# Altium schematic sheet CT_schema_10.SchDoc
size 389 x 278 mm
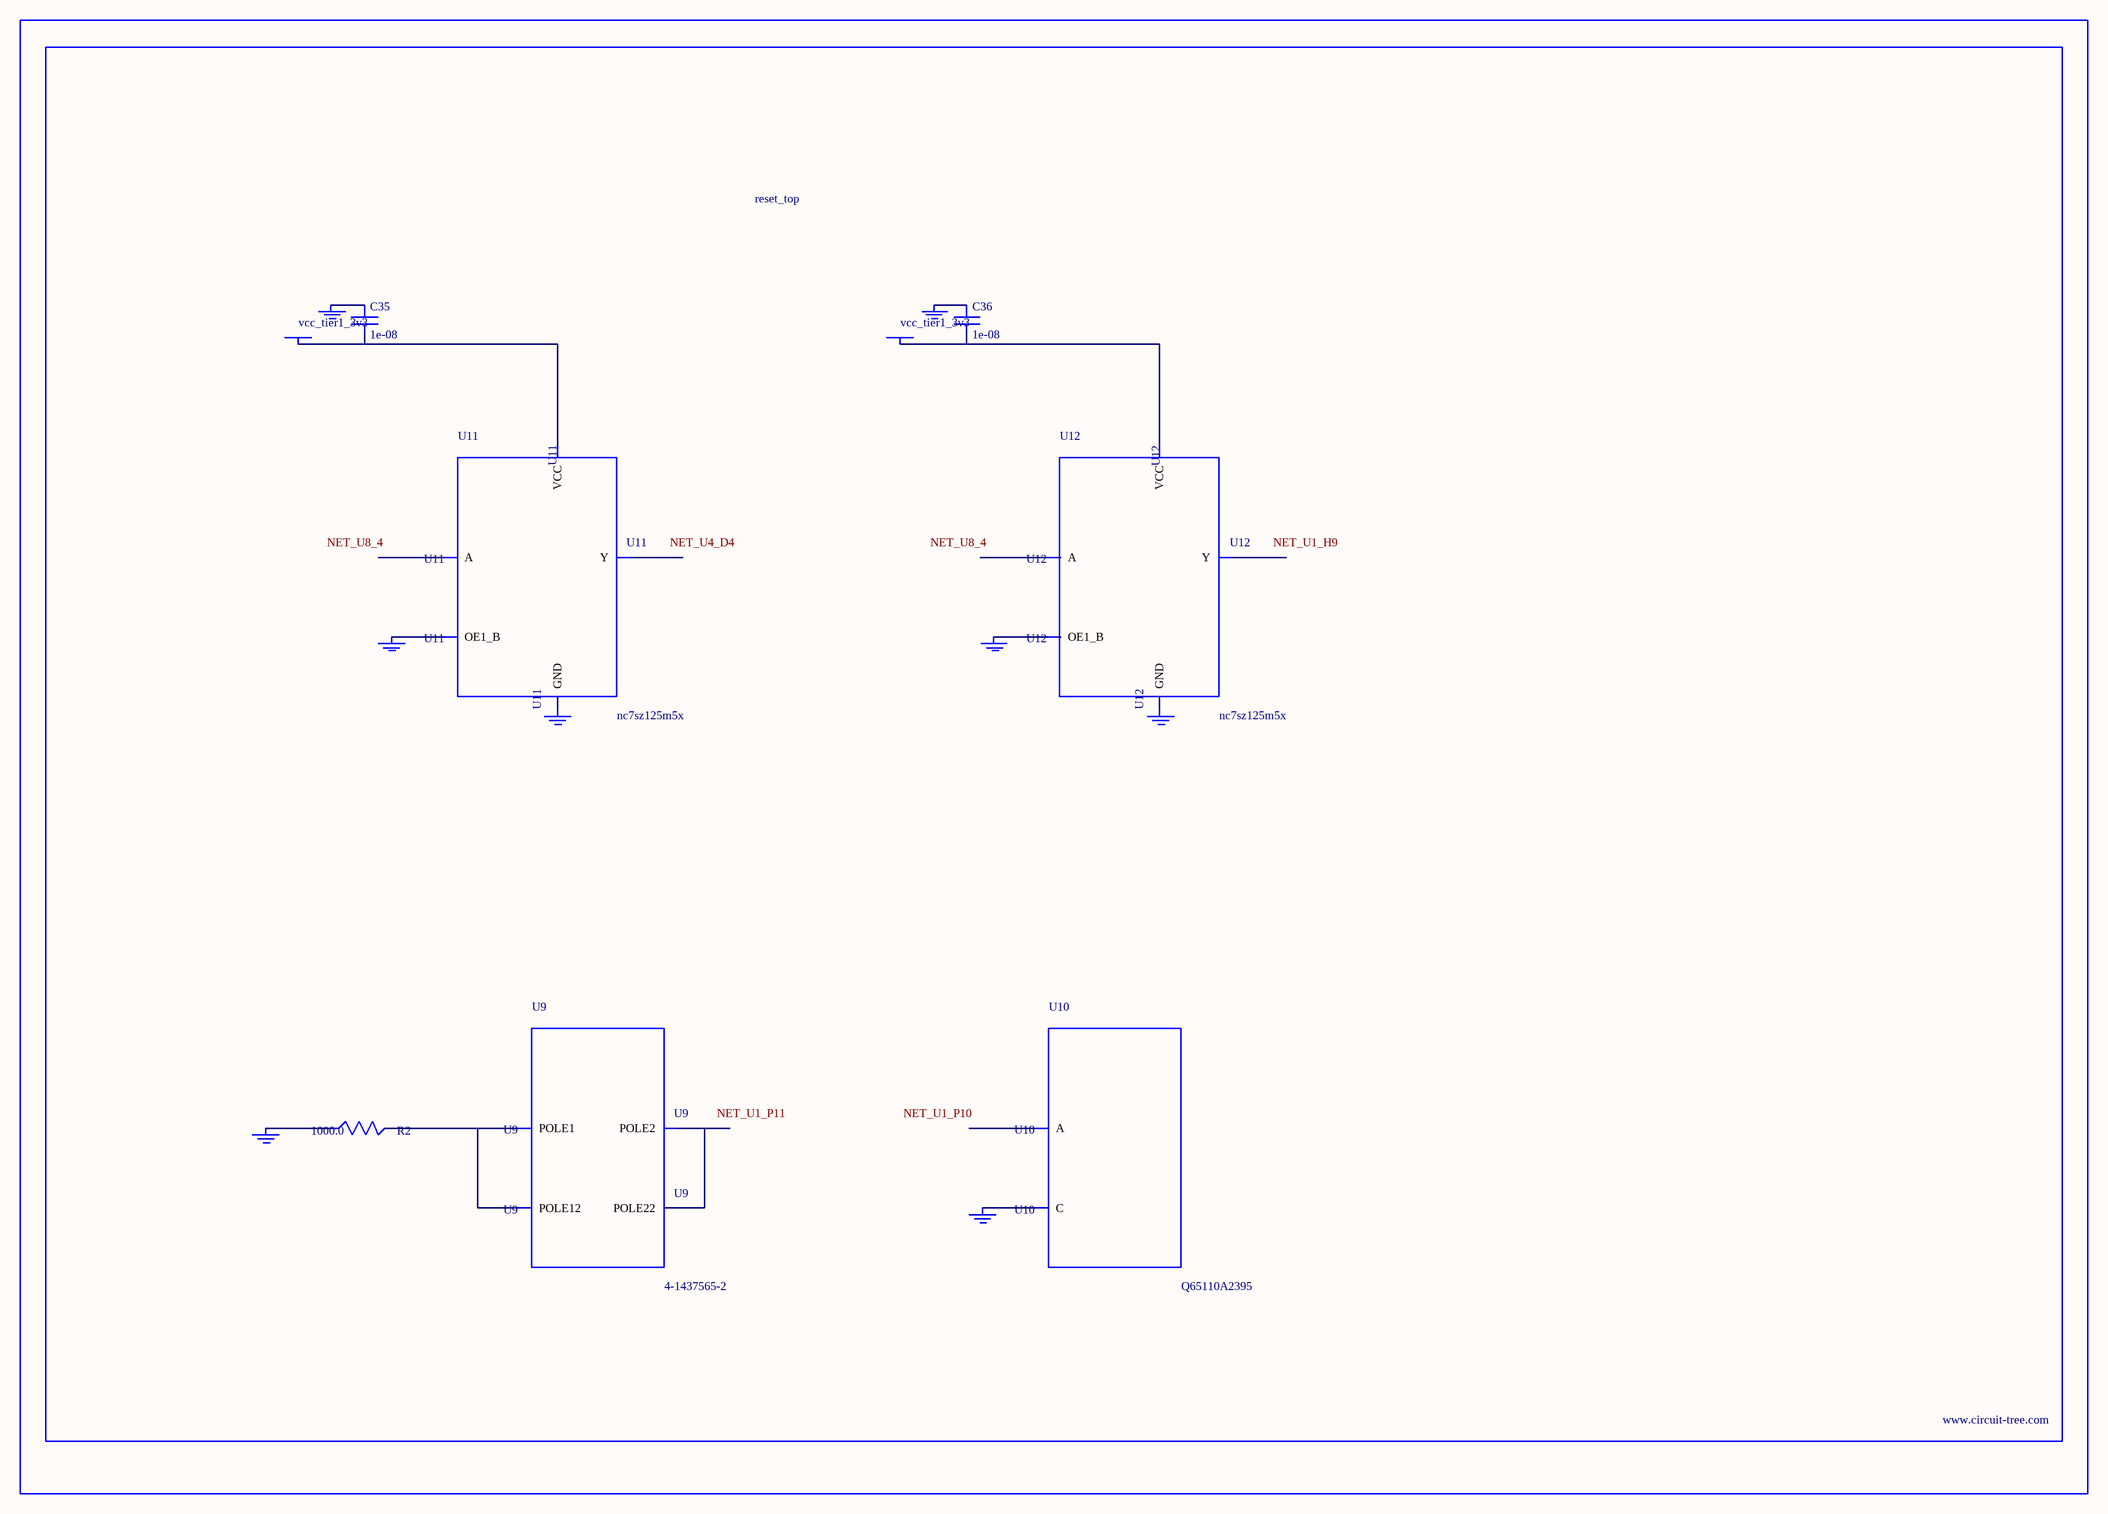
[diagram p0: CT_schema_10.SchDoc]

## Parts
BORDER9  (no value)
C35  1e-08  [C0402]
C36  1e-08  [C0402]
GND_INSTANCE_9_0  (no value)
GND_INSTANCE_9_1  (no value)
GND_INSTANCE_9_2  (no value)
GND_INSTANCE_9_3  (no value)
GND_INSTANCE_9_4  (no value)
GND_INSTANCE_9_5  (no value)
GND_INSTANCE_9_6  (no value)
GND_INSTANCE_9_7  (no value)
POWER_INSTANCE_9_0  vcc_tier1_3v3
POWER_INSTANCE_9_1  vcc_tier1_3v3
R2  1000.0  [R0603]
U9  4-1437565-2  [SW_4-1437565-2]
U10  Q65110A2395  [LGM67K-G1J2-24-Z]
U11  nc7sz125m5x  [NC7SZ125M5X]
U12  nc7sz125m5x  [NC7SZ125M5X]

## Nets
NetC35_1: C35.1 GND_INSTANCE_9_2.0(GND)
NetC35_2: C35.2 POWER_INSTANCE_9_0.0(PWR) U11.5(VCC)
NetC36_1: C36.1 GND_INSTANCE_9_5.0(GND)
NetC36_2: C36.2 POWER_INSTANCE_9_1.0(PWR) U12.5(VCC)
NetGND_INSTANCE_9_0_0: GND_INSTANCE_9_0.0(GND) R2.1
NetGND_INSTANCE_9_1_0: GND_INSTANCE_9_1.0(GND) U10.C
NetGND_INSTANCE_9_3_0: GND_INSTANCE_9_3.0(GND) U11.1(OE1_B)
NetGND_INSTANCE_9_4_0: GND_INSTANCE_9_4.0(GND) U11.3(GND)
NetGND_INSTANCE_9_6_0: GND_INSTANCE_9_6.0(GND) U12.1(OE1_B)
NetGND_INSTANCE_9_7_0: GND_INSTANCE_9_7.0(GND) U12.3(GND)
NetR2_2: R2.2 U9.1(POLE1) U9.2(POLE12)
NetU9_3: U9.3(POLE2) U9.4(POLE22)

Not connected (* = marked no-connect by the designer): U10 A; U11 2(A) 4(Y); U12 2(A) 4(Y)

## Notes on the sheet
- Labels drawn without touching a wire or pin: NET_U1_H9, NET_U1_P10, NET_U1_P11, NET_U4_D4, NET_U8_4

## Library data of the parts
BORDER9 = BORDER_PAGE9
C35 C36 = C0402C103K3RAC
GND_INSTANCE_9_0-GND_INSTANCE_9_7 = GND
POWER_INSTANCE_9_0 POWER_INSTANCE_9_1 = PWR
R2 = RC0603JR-071KL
